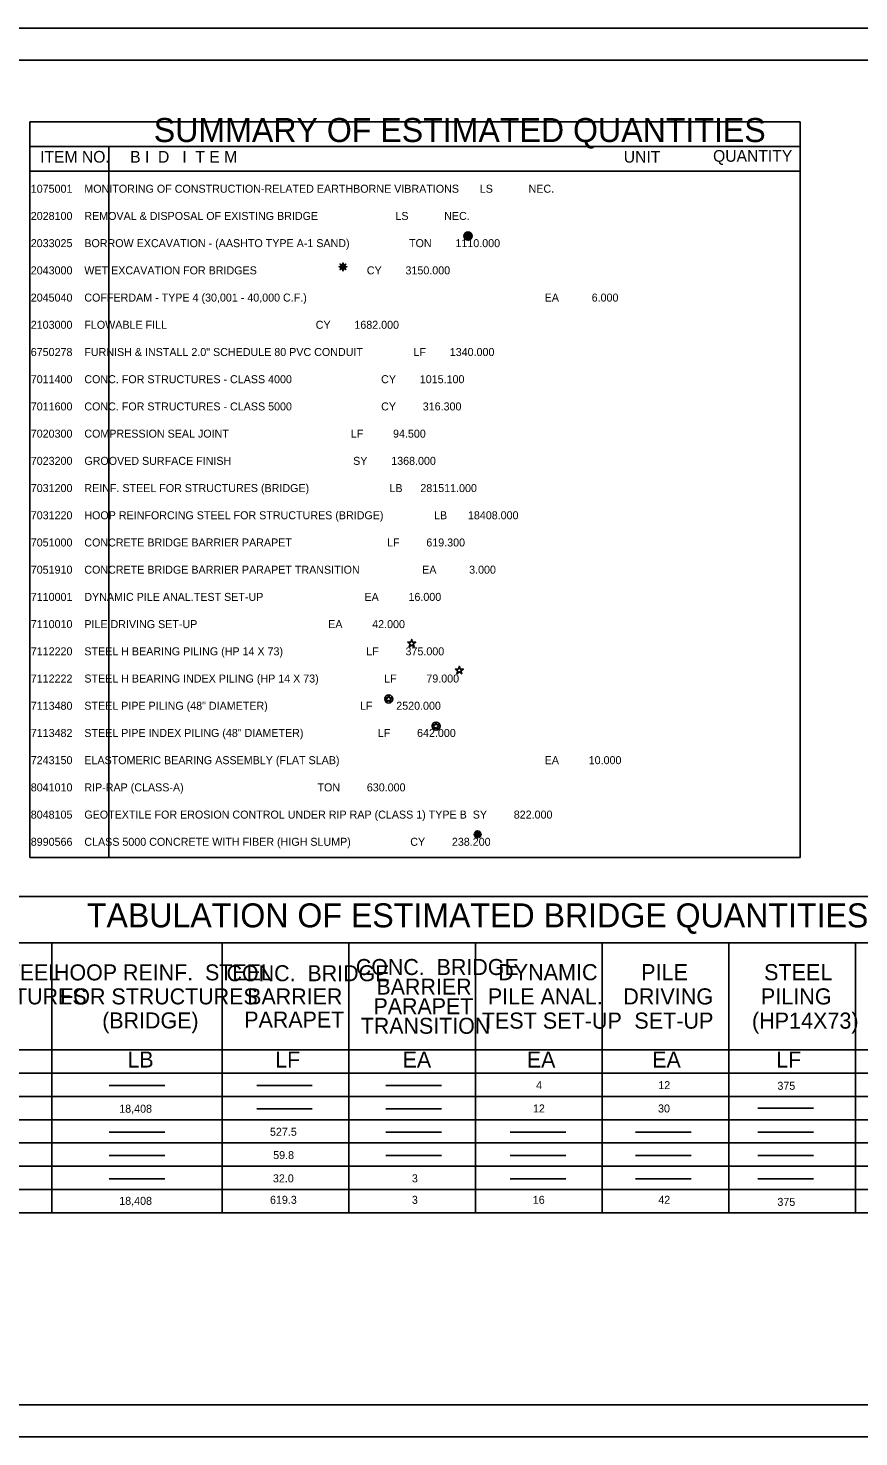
# Model space of a CAD drawing. Extents: x 1334.3 to 1370.4, y 717.9 to 739.9.
# Drawn here: x 1347.02 to 1360, y 717.86 to 739.87 of the extents above; entities that cross this region are included whole.
import ezdxf

# ---------------------------------------------------------------- set-up
doc = ezdxf.new("R2010")
doc.units = 0
for name, color, linetype in [('BR_AUTO DIMENSION', 7, 'Continuous'), ('BR_BORDER LINES', 7, 'Continuous'), ('BR_TABLE LINES', 7, 'Continuous'), ('BR_TEXT', 7, 'Continuous'), ('Default', 7, 'Continuous'), ('RD_SHT_IplotShp', 7, 'Continuous')]:
    doc.layers.add(name, color=color, linetype=linetype)

# ---------------------------------------------------------------- blocks, each defined once
blk = doc.blocks.new('BUBB')
at = {"layer": 'Default'}
for p, q in [((1.433, 5.4711), (-3.2566, 2.0842)), ((-3.2566, 2.0842), (1.954, 5.0803)), ((-2.9961, 4.5593), (0, 6.2527)), ((0, 6.2527), (-2.9961, 3.7777)), ((-2.9961, 3.7777), (0.6514, 5.9922)), ((0.6514, 5.9922), (-2.9961, 3.1264)), ((-2.9961, 3.1264), (1.433, 5.4711)), ((1.954, 5.0803), (-2.475, 1.1724)), ((-2.475, 1.1724), (2.4751, 4.0382)), ((2.4751, 4.0382), (-1.4329, 1.1724)), ((-1.4329, 1.1724), (2.6054, 3.1264)), ((2.6054, 3.1264), (-1.1723, 0.6513)), ((-1.1723, 0.6513), (2.6054, 2.475)), ((2.6054, 2.475), (0.1303, 0.6513))]:
    blk.add_line(p, q, dxfattribs=at)
blk.add_circle((-0.1667, 3.3444), 3.2509, dxfattribs=at)

msp = doc.modelspace()

# ---------------------------------------------------------------- linework, layer by layer
at = {"layer": 'BR_AUTO DIMENSION'}
for points in [[(1351.923, 736.166), (1351.896, 736.183), (1351.913, 736.156)], [(1351.947, 736.17), (1351.94, 736.201), (1351.933, 736.17)], [(1351.947, 736.17), (1351.94, 736.139), (1351.933, 736.17)], [(1351.967, 736.156), (1351.985, 736.183), (1351.957, 736.166)], [(1351.909, 736.146), (1351.878, 736.139), (1351.909, 736.132)], [(1351.913, 736.122), (1351.896, 736.095), (1351.923, 736.112)], [(1351.909, 736.146), (1351.94, 736.139), (1351.909, 736.132)], [(1351.923, 736.166), (1351.94, 736.139), (1351.913, 736.156)], [(1351.913, 736.122), (1351.94, 736.139), (1351.923, 736.112)], [(1351.933, 736.108), (1351.94, 736.139), (1351.947, 736.108)], [(1351.933, 736.108), (1351.94, 736.076), (1351.947, 736.108)], [(1351.967, 736.156), (1351.94, 736.139), (1351.957, 736.166)], [(1351.972, 736.132), (1351.94, 736.139), (1351.972, 736.146)], [(1351.957, 736.112), (1351.94, 736.139), (1351.967, 736.122)], [(1351.957, 736.112), (1351.985, 736.095), (1351.967, 736.122)], [(1351.972, 736.132), (1352.003, 736.139), (1351.972, 736.146)]]:
    msp.add_lwpolyline(points, close=True, dxfattribs=at)
at = {"layer": 'BR_BORDER LINES'}
for p, q in [((1334.334, 739.866), (1370.334, 739.866)), ((1369.834, 739.365), (1336.167, 739.365)), ((1347.053, 738.402), (1359.082, 738.402)), ((1347.053, 726.912), (1347.053, 738.402)), ((1359.082, 738.402), (1359.082, 726.912)), ((1347.053, 738.018), (1359.082, 738.018)), ((1347.053, 726.912), (1359.082, 726.912)), ((1369.834, 726.305), (1336.167, 726.305)), ((1353.62, 726.305), (1348.224, 726.305)), ((1369.834, 725.579), (1336.167, 725.579)), ((1369.834, 721.363), (1336.167, 721.363)), ((1336.167, 718.365), (1369.834, 718.365)), ((1334.334, 717.866), (1370.334, 717.866))]:
    msp.add_line(p, q, dxfattribs=at)
at = {"layer": 'BR_TABLE LINES'}
for p, q in [((1348.283, 726.912), (1348.283, 738.018)), ((1347.053, 737.634), (1359.082, 737.634)), ((1347.392, 725.579), (1347.392, 721.363)), ((1347.392, 725.579), (1347.392, 721.363)), ((1350.056, 725.579), (1350.056, 721.363)), ((1352.033, 725.579), (1352.033, 721.363)), ((1354.011, 725.579), (1354.011, 721.363)), ((1355.989, 725.579), (1355.989, 721.363)), ((1357.966, 725.579), (1357.966, 721.363)), ((1359.944, 725.579), (1359.944, 721.363)), ((1369.834, 723.91), (1345.152, 723.91)), ((1369.834, 723.546), (1345.152, 723.546)), ((1369.834, 723.182), (1336.167, 723.182)), ((1369.834, 722.818), (1345.152, 722.818)), ((1369.834, 722.455), (1340.47, 722.455)), ((1369.834, 722.091), (1345.152, 722.091)), ((1369.834, 721.727), (1345.152, 721.727))]:
    msp.add_line(p, q, dxfattribs=at)
at = {"layer": 'BR_TEXT'}
for p, q in [((1354.107, 727.275), (1353.98, 727.275)), ((1353.98, 727.275), (1354.107, 727.275)), ((1354.107, 727.275), (1353.98, 727.275)), ((1353.98, 727.275), (1354.107, 727.275)), ((1354.099, 727.243), (1353.989, 727.306)), ((1354.099, 727.306), (1353.989, 727.243)), ((1353.989, 727.306), (1354.099, 727.243)), ((1353.989, 727.243), (1354.099, 727.306)), ((1354.099, 727.243), (1353.989, 727.306)), ((1354.099, 727.306), (1353.989, 727.243)), ((1353.989, 727.306), (1354.099, 727.243)), ((1353.989, 727.243), (1354.099, 727.306)), ((1354.076, 727.219), (1354.012, 727.33)), ((1354.076, 727.33), (1354.012, 727.219)), ((1354.012, 727.33), (1354.076, 727.219)), ((1354.012, 727.219), (1354.076, 727.33)), ((1354.076, 727.219), (1354.012, 727.33)), ((1354.076, 727.33), (1354.012, 727.219)), ((1354.012, 727.33), (1354.076, 727.219)), ((1354.044, 727.339), (1354.044, 727.212)), ((1354.044, 727.211), (1354.044, 727.338)), ((1354.044, 727.338), (1354.044, 727.211)), ((1354.044, 727.211), (1354.044, 727.338)), ((1354.044, 727.338), (1354.044, 727.211)), ((1348.29, 723.35), (1349.158, 723.35)), ((1350.595, 723.35), (1351.462, 723.35)), ((1352.612, 723.35), (1353.48, 723.35)), ((1350.595, 722.986), (1351.462, 722.986)), ((1352.612, 722.986), (1353.48, 722.986)), ((1358.419, 722.997), (1359.287, 722.997)), ((1348.29, 722.622), (1349.158, 722.622)), ((1352.612, 722.622), (1353.48, 722.622)), ((1354.552, 722.622), (1355.42, 722.622)), ((1356.51, 722.622), (1357.378, 722.622)), ((1358.419, 722.622), (1359.287, 722.622)), ((1348.29, 722.259), (1349.158, 722.259)), ((1352.612, 722.259), (1353.48, 722.259)), ((1354.552, 722.259), (1355.42, 722.259)), ((1356.51, 722.259), (1357.378, 722.259)), ((1358.419, 722.258), (1359.287, 722.258)), ((1348.29, 721.895), (1349.158, 721.895)), ((1354.552, 721.895), (1355.42, 721.895)), ((1356.51, 721.895), (1357.378, 721.895)), ((1358.419, 721.895), (1359.287, 721.895))]:
    msp.add_line(p, q, dxfattribs=at)
for points in [[(1352.991, 730.249), (1352.976, 730.204), (1353.014, 730.232), (1353.051, 730.204), (1353.037, 730.248), (1353.076, 730.276), (1353.029, 730.276), (1353.015, 730.32), (1353, 730.277), (1352.952, 730.277)], [(1353.735, 729.829), (1353.72, 729.784), (1353.758, 729.812), (1353.795, 729.784), (1353.781, 729.828), (1353.821, 729.857), (1353.773, 729.857), (1353.759, 729.901), (1353.744, 729.857), (1353.696, 729.857)], [(1352.631, 729.38), (1352.616, 729.335), (1352.654, 729.363), (1352.691, 729.335), (1352.677, 729.379), (1352.716, 729.407), (1352.668, 729.407), (1352.655, 729.452), (1352.64, 729.408), (1352.592, 729.408)], [(1353.37, 728.956), (1353.355, 728.911), (1353.393, 728.939), (1353.43, 728.911), (1353.416, 728.955), (1353.456, 728.983), (1353.408, 728.983), (1353.394, 729.027), (1353.379, 728.984), (1353.331, 728.984)]]:
    msp.add_lwpolyline(points, close=True, dxfattribs=at)
for centre in [(1352.656, 729.389), (1353.395, 728.964)]:
    msp.add_circle(centre, 0.0636, dxfattribs=at)
at = {"layer": 'RD_SHT_IplotShp'}
msp.add_lwpolyline([(1334.334, 739.865), (1370.334, 739.865), (1370.334, 717.865), (1334.334, 717.865)], close=True, dxfattribs=at)

# ---------------------------------------------------------------- block references
at = {"layer": 'BR_TEXT', "xscale": 0.020000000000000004, "yscale": 0.020000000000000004, "rotation": -90.00000000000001}
msp.add_blockref('BUBB', (1353.826, 736.617), dxfattribs=at)

# ---------------------------------------------------------------- texts
at = {"layer": 'BR_TEXT'}
for s, height, p in [('SUMMARY OF ESTIMATED QUANTITIES ', 0.375, (1348.986, 738.088)), ('ITEM NO.', 0.183, (1347.211, 737.766)), ('B I  D   I  T E M', 0.183, (1348.617, 737.766)), ('UNIT', 0.183, (1356.326, 737.766)), ('QUANTITY', 0.183, (1357.72, 737.78)), ('   1075001    MONITORING OF CONSTRUCTION-RELATED EARTHBORNE VIBRATIONS       LS            NEC.', 0.125, (1346.926, 737.296)), ('   2028100    REMOVAL & DISPOSAL OF EXISTING BRIDGE                          LS            NEC.', 0.125, (1346.926, 736.871)), ('   2033025    BORROW EXCAVATION - (AASHTO TYPE A-1 SAND)                    TON        1110.000', 0.125, (1346.926, 736.446)), ('   2043000    WET EXCAVATION FOR BRIDGES                                     CY        3150.000', 0.125, (1346.926, 736.021)), ('   2045040    COFFERDAM - TYPE 4 (30,001 - 40,000 C.F.)', 0.125, (1346.926, 735.596)), ('                 EA           6.000', 0.125, (1354.301, 735.596)), ('   2103000    FLOWABLE FILL                                                  CY        1682.000', 0.125, (1346.926, 735.171)), ('   6750278    FURNISH & INSTALL 2.0" SCHEDULE 80 PVC CONDUIT                 LF        1340.000', 0.125, (1346.926, 734.746)), ('   7011400    CONC. FOR STRUCTURES - CLASS 4000                              CY        1015.100', 0.125, (1346.926, 734.321)), ('   7011600    CONC. FOR STRUCTURES - CLASS 5000                              CY         316.300', 0.125, (1346.926, 733.896)), ('   7020300    COMPRESSION SEAL JOINT                                         LF          94.500', 0.125, (1346.926, 733.471)), ('   7023200    GROOVED SURFACE FINISH                                         SY        1368.000', 0.125, (1346.926, 733.046)), ('   7031200    REINF. STEEL FOR STRUCTURES (BRIDGE)                           LB      281511.000', 0.125, (1346.926, 732.621)), ('   7031220    HOOP REINFORCING STEEL FOR STRUCTURES (BRIDGE)                 LB       18408.000', 0.125, (1346.926, 732.196)), ('   7051000    CONCRETE BRIDGE BARRIER PARAPET                                LF         619.300', 0.125, (1346.926, 731.771)), ('   7051910    CONCRETE BRIDGE BARRIER PARAPET TRANSITION                     EA           3.000', 0.125, (1346.926, 731.346)), ('   7110001    DYNAMIC PILE ANAL.TEST SET-UP                                  EA          16.000', 0.125, (1346.926, 730.921)), ('   7110010    PILE DRIVING SET-UP                                            EA          42.000', 0.125, (1346.926, 730.496)), ('   7112220    STEEL H BEARING PILING (HP 14 X 73)                            LF         375.000', 0.125, (1346.926, 730.071)), ('   7112222    STEEL H BEARING INDEX PILING (HP 14 X 73)                      LF          79.000', 0.125, (1346.926, 729.646)), ('   7113480    STEEL PIPE PILING (48" DIAMETER)                               LF        2520.000', 0.125, (1346.926, 729.221)), ('   7113482    STEEL PIPE INDEX PILING (48" DIAMETER)                         LF         642.000', 0.125, (1346.926, 728.796)), ('   7243150    ELASTOMERIC BEARING ASSEMBLY (FLAT SLAB)', 0.125, (1346.926, 728.371)), ('                 EA          10.000', 0.125, (1354.301, 728.371)), ('   8041010    RIP-RAP (CLASS-A)                                             TON         630.000', 0.125, (1346.926, 727.946)), ('   8048105    GEOTEXTILE FOR EROSION CONTROL UNDER RIP RAP (CLASS 1) TYPE B  SY         822.000', 0.125, (1346.926, 727.521)), ('   8990566    CLASS 5000 CONCRETE WITH FIBER (HIGH SLUMP)                    CY         238.200', 0.125, (1346.926, 727.096)), ('TABULATION OF ESTIMATED BRIDGE QUANTITIES', 0.375, (1347.941, 725.822)), ('REINF.  STEEL', 0.25, (1345.185, 724.994)), ('HOOP REINF.  STEEL', 0.25, (1347.428, 724.994)), ('CONC.  BRIDGE', 0.24993, (1350.123, 724.981)), ('CONC.  BRIDGE', 0.24993, (1352.141, 725.078)), ('DYNAMIC ', 0.2518, (1354.364, 724.996)), ('PILE ', 0.2518, (1356.597, 724.996)), ('STEEL', 0.2518, (1358.517, 724.996)), ('BARRIER', 0.2499, (1352.463, 724.772)), ('FOR STRUCTURES', 0.25, (1344.854, 724.619)), ('FOR STRUCTURES', 0.25, (1347.526, 724.619)), ('BARRIER', 0.2499, (1350.445, 724.619)), ('PILE ANAL.', 0.2518, (1354.202, 724.618)), ('DRIVING ', 0.2518, (1356.318, 724.618)), ('PILING ', 0.2518, (1358.467, 724.618)), ('(BRIDGE)', 0.25, (1348.181, 724.244)), ('PARAPET', 0.2499, (1350.4, 724.257)), ('PARAPET', 0.2499, (1352.417, 724.466)), ('TRANSITION', 0.2499, (1352.218, 724.16)), ('TEST SET-UP', 0.25178, (1354.107, 724.24)), ('SET-UP', 0.2518, (1356.491, 724.24)), ('(HP14X73)', 0.2518, (1358.327, 724.24)), ('LB', 0.25, (1348.575, 723.633)), ('LF', 0.2499, (1350.882, 723.632)), ('EA', 0.2499, (1352.872, 723.632)), ('EA', 0.2499, (1354.812, 723.632)), ('EA', 0.2499, (1356.77, 723.632)), ('LF', 0.25, (1358.707, 723.632)), ('4', 0.125, (1354.957, 723.295)), ('12', 0.125, (1356.865, 723.295)), ('375', 0.125, (1358.725, 723.285)), ('18,408', 0.125, (1348.447, 722.927)), ('12', 0.125, (1354.907, 722.931)), ('30', 0.125, (1356.861, 722.931)), ('527.5', 0.125, (1350.801, 722.567)), ('59.8', 0.125, (1350.851, 722.203)), ('32.0', 0.125, (1350.847, 721.839)), ('3', 0.125, (1353.017, 721.839)), ('18,408', 0.125, (1348.447, 721.488)), ('619.3', 0.125, (1350.801, 721.504)), ('3', 0.125, (1353.017, 721.504)), ('16', 0.125, (1354.905, 721.504)), ('42', 0.125, (1356.865, 721.504)), ('375', 0.125, (1358.725, 721.472))]:
    msp.add_text(s, height=height, dxfattribs=at).set_placement(p)

doc.saveas('drawing.dxf')
